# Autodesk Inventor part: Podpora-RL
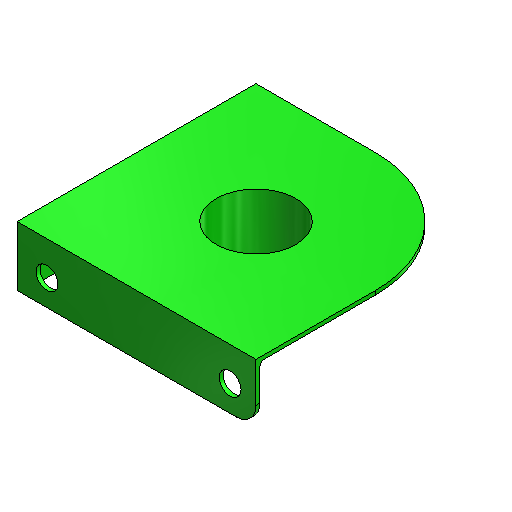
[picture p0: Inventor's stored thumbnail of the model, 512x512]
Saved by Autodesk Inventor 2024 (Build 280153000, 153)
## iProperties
Company: ATC
Shininess: 20.0
Angle Display Precision: 2
Document Length Units: 11269
Document Angle Units: 11279
Document Time Units: 11290
Document Mass Units: 11283
Document Length Units Precision: 3
Document Angle Units Precision: 2
Created: 2023-03
Part Number: Podpora-RL
Material: Stal węglowa
Document SubType Name: Modelowanie
Designer: Andrzej Jaskulski
Density: 7.87 g/cm^3
Stock Number: Podpora-RL
Appearance: LED — zielone włączone
Checked By: A.J.
Engr Approved By: Andrzej Jaskulski
Mfg Approved By: Andrzej Jaskulski
Authority: A.J.
Density: 0.0
Volumn: 0.0
Area: 0.0
PropertySet Name: Model Information
Control State: 0
Master: False
Checked Out: False
Title: A.J.: Kurs R2024-MEP
Author: Andrzej Jaskulski
Revision Number: 1/24
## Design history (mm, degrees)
node "Bryła1"
node "Początek"
  node "Płaszczyzna YZ"
  node "Płaszczyzna XZ"
  node "Płaszczyzna XY"
  node "Oś X"
  node "Oś Y"
  node "Oś Z"
node "Podpora-RP" dims "d13" = 10
feature "Bryła1::Podpora-RP" dims "d13" = 10
node "Korpusy bryłowe"
node "Korpusy powierzchniowe"
node "Punkt środkowy"
tag "Bryła wyprowadzona3"
